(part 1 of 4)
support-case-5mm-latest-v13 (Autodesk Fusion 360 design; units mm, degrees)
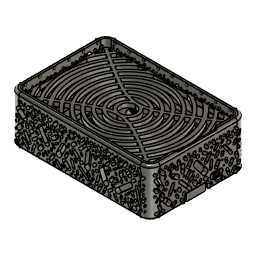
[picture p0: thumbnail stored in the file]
parameter "thick" = 1.5
sketch "Sketch1" plane through (0, 0, 0) normal (0, 0, 1) x axis (1, 0, 0)
  line L1 (86.9, 56.002) -> (1.9, 56.002)
  line L2 (86.9, -0.0138) -> (86.9, 56.002)
  line L3 (1.9, -0.0138) -> (86.9, -0.0138)
  line L4 (1.9, 56.002) -> (1.9, -0.0138)
  line L5 (0.9, 57.002) -> (0.9, -1.0138)
  line L6 (87.9, 57.002) -> (0.9, 57.002)
  line L7 (87.9, -1.0138) -> (87.9, 57.002)
  line L8 (0.9, -1.0138) -> (87.9, -1.0138)
  line L9 (-1.9, 59.802) -> (-1.9, -3.8138)
  line L10 (90.7, 59.802) -> (-1.9, 59.802)
  line L11 (90.7, -3.8138) -> (90.7, 59.802)
  line L12 (-1.9, -3.8138) -> (90.7, -3.8138)
  line L13 (-0.1, -2.0138) -> (88.9, -2.0138)
  line L14 (-0.1, 58.002) -> (-0.1, -2.0138)
  line L15 (88.9, 58.002) -> (-0.1, 58.002)
  line L16 (88.9, -2.0138) -> (88.9, 58.002)
  horizontal L1
  vertical L2
  horizontal L3
  vertical L4
  dimension "d2" = -1
  dimension "d3" = -3.8 (= "-1 mm - 2.8 mm")
  dimension "d4" = -2
extrude "Extrude1" new body sketch "Sketch1" profile of L8 L5 L6 L7 L12 L9 L10 L11 L14 L13 L15 L16 along normal blind 20
sketch "Sketch2" plane through (0, 0, 0) normal (1, 0, 0) x axis (0, 1, 0)
  line L1 (40.9881, 18.9973) -> (54.0881, 18.9973)
  line L2 (40.9881, 2.9973) -> (40.9881, 18.9973)
  line L3 (54.0881, 2.9973) -> (40.9881, 2.9973)
  line L4 (54.0881, 18.9973) -> (54.0881, 2.9973)
  line L5 (22.95, 19) -> (36.05, 19)
  line L6 (22.95, 3) -> (22.95, 19)
  line L7 (36.05, 3) -> (22.95, 3)
  line L8 (36.05, 19) -> (36.05, 3)
  line L9 (2.05, 3) -> (17.95, 3)
  line L10 (2.05, 16.5) -> (2.05, 3)
  line L11 (17.95, 16.5) -> (2.05, 16.5)
  line L12 (17.95, 3) -> (17.95, 16.5)
  point P2 (54.0881, 18.9973)
  point P3 (40.9881, 18.9973)
  point P5 (54.0881, 2.9973)
  point P6 (36.05, 19)
  point P7 (22.95, 19)
  point P9 (36.05, 3)
  point P10 (17.95, 3)
  point P11 (2.05, 3)
  point P13 (17.95, 16.5)
  horizontal L1
  vertical L2
  horizontal L3
  vertical L4
  horizontal L5
  vertical L6
  horizontal L7
  vertical L8
  horizontal L9
  vertical L10
  horizontal L11
  vertical L12
  dimension "d7" distance P2 P3 = 13.1
  dimension "d8" distance P2 P5 = 16
  dimension "d9" distance P6 P7 = 13.1
  dimension "d10" distance P6 P9 = 16
  dimension "d11" distance P10 P11 = 15.9
  dimension "d12" distance P10 P13 = 13.5
work_plane "WorkPlane1" AlongDistance 57
sketch "Sketch3" plane through (0, 57, 0) normal (0, 1, 0) x axis (1, 0, 0)
  line L1 (43.9, -6) -> (51, -6)
  line L2 (43.9, -3) -> (43.9, -6)
  line L3 (51, -3) -> (43.9, -3)
  line L4 (51, -6) -> (51, -3)
  line L5 (57.25, -6) -> (64.35, -6)
  line L6 (57.25, -3) -> (57.25, -6)
  line L7 (64.35, -3) -> (57.25, -3)
  line L8 (64.35, -6) -> (64.35, -3)
  line L9 (71.05, -6.3) -> (80.05, -6.3)
  line L10 (71.05, -3) -> (71.05, -6.3)
  line L11 (80.05, -3) -> (71.05, -3)
  line L12 (80.05, -6.3) -> (80.05, -3)
  circle C1 centre (33.2511, -6.0518) radius 3
  point P3 (51, -6)
  point P4 (43.9, -6)
  point P6 (51, -3)
  point P7 (64.35, -6)
  point P8 (57.25, -6)
  point P11 (80.05, -6.3)
  point P12 (71.05, -6.3)
  point P14 (80.05, -3)
  horizontal L1
  vertical L2
  horizontal L3
  vertical L4
  horizontal L5
  vertical L6
  horizontal L7
  vertical L8
  horizontal L9
  vertical L10
  horizontal L11
  vertical L12
  dimension "d14" diameter C1 = 6
  dimension "d15" distance P3 P4 = 7.1
  dimension "d16" distance P3 P6 = 3
  dimension "d17" distance P7 P8 = 7.1
  dimension "d18" distance P11 P12 = 9
  dimension "d19" distance P11 P14 = 3.3
work_plane "WorkPlane2" AlongDistance 87
sketch "Sketch4" plane through (87, 0, 0) normal (1, 0, 0) x axis (0, 1, 0)
  line L1 (34.6, 1.4) -> (19.9875, 1.4)
  line L2 (34.6, 0) -> (34.6, 1.4)
  line L3 (19.9875, 0) -> (34.6, 0)
  line L4 (19.9875, 1.4) -> (19.9875, 0)
  horizontal L1
  vertical L2
  horizontal L3
  vertical L4
fillet "Fillet1" radius 3.5 6.5
extrude "Extrude2" cut sketch "Sketch3" along normal blind 18
extrude "Extrude3" add sketch "Sketch1" profile of L1 L2 L3 L4 L8 L5 L6 L7 blind -2.8
sketch "Sketch5" plane through (0, 0, 0) normal (0, 0, 1) x axis (1, 0, 0)
  circle C1 centre (83.4, 52.5) radius 3
  circle C2 centre (25.4038, 52.5109) radius 3
  circle C3 centre (25.4086, 3.5211) radius 3
  circle C4 centre (83.4, 3.5) radius 3
  dimension "d27" diameter C1 = 6
  dimension "d28" diameter C2 = 6
  dimension "d29" diameter C3 = 6
  dimension "d30" diameter C4 = 6
extrude "Extrude4" add sketch "Sketch5" along normal blind 1.4
sketch "Sketch6" plane through (0, 0, 1.4) normal (0, 0, 1) x axis (-1, 0, 0)
  circle C1 centre (-83.4, -52.5) radius 3
  circle C2 centre (-25.4086, -3.5211) radius 1.375
  circle C3 centre (-25.4086, -3.5211) radius 3
  circle C4 centre (-83.4, -3.5) radius 1.375
  circle C5 centre (-83.4, -3.5) radius 3
  circle C6 centre (-83.4, -52.5) radius 1.375
  circle C7 centre (-25.4038, -52.5109) radius 1.375
  circle C8 centre (-25.4038, -52.5109) radius 3
  concentric C2 C3
  concentric C4 C5
  concentric C1 C6
  concentric C7 C8
  dimension "d33" diameter C2 = 2.75
  dimension "d34" diameter C4 = 2.75
  dimension "d35" diameter C6 = 2.75
  dimension "d36" diameter C7 = 2.75
sketch "Sketch7" plane through (0, 59.802, 0) normal (0, 1, 0) x axis (-1, 0, 0)
  line L1 (-64.35, 6) -> (-64.35, 3)
  line L2 (-57.25, 6) -> (-64.35, 6)
  line L3 (-57.25, 3) -> (-57.25, 6)
  line L4 (-64.35, 3) -> (-57.25, 3)
  line L5 (-51, 6) -> (-51, 3)
  line L6 (-43.9, 6) -> (-51, 6)
  line L7 (-43.9, 3) -> (-43.9, 6)
  line L8 (-51, 3) -> (-43.9, 3)
  line L9 (-80.05, 6.3) -> (-80.05, 3)
  line L10 (-71.05, 6.3) -> (-80.05, 6.3)
  line L11 (-71.05, 3) -> (-71.05, 6.3)
  line L12 (-80.05, 3) -> (-71.05, 3)
  line L13 (-4.6, -2.8) -> (-84.2, -2.8)
  line L14 (-84.2, 20) -> (-4.6, 20)
  line L15 (-83.55, 3) -> (-80.05, 3)
  line L16 (-83.55, -0.5) -> (-83.55, 3)
  line L17 (-80.05, -0.5) -> (-83.55, -0.5)
  line L18 (-80.05, 3) -> (-80.05, -0.5)
  line L19 (-31.1297, 8.1731) -> (-33.2511, 6.0518)
  line L20 (-30.2511, 6.0518) -> (-33.2511, 6.0518)
  line L21 (-26.7507, 8.1731) -> (-31.1297, 8.1731)
  line L22 (-26.7507, 12.5521) -> (-26.7507, 8.1731)
  line L23 (-31.1297, 12.5521) -> (-26.7507, 12.5521)
  line L24 (-31.1297, 8.1731) -> (-31.1297, 12.5521)
  line L25 (-26.7507, -0.5) -> (-83.55, -0.5)
  line L26 (-26.7507, 12.5521) -> (-26.7507, -0.5)
  line L27 (-83.55, 12.5521) -> (-26.7507, 12.5521)
  line L28 (-83.55, -0.5) -> (-83.55, 12.5521)
  line L29 (-4.6, 20) -> (-4.6, -2.8)
  line L30 (-84.2, -2.8) -> (-84.2, 20)
  circle C1 centre (-33.2511, 6.0518) radius 3
  point P10 (-80.05, 3)
  point P19 (-80.05, 3)
  point P14 (-33.2511, 6.0518)
  point P23 (-33.2511, 6.0518)
  point P24 (-31.1297, 8.1731)
  point P20 (-83.55, 3)
  point P22 (-80.05, -0.5)
  point P26 (-26.7507, 8.1731)
  point P28 (-31.1297, 12.5521)
  horizontal L15
  vertical L16
  horizontal L17
  vertical L18
  coincident P10 P19
  horizontal L20
  coincident P14 P23
  coincident C1 P24
  horizontal L21
  vertical L22
  horizontal L23
  vertical L24
  horizontal L25
  vertical L26
  horizontal L27
  vertical L28
  dimension "d37" distance P19 P20 = 3.5
  dimension "d38" distance P19 P22 = 3.5
  dimension "d39" angle L19 L20 = 45
  dimension "d40" distance P24 P26 = 4.379 (= "3.5 mm - 2.621 mm + 3.5 mm")
  dimension "d41" distance P24 P28 = 4.379 (= "4 mm + 3.5 mm - 3.121 mm")
extrude "Extrude5" cut sketch "Sketch7" profile of L1 L2 L3 L4 L5 L6 L7 L8 L9 L10 L11 L12 C1 L15 L16 L17 L18 L21 L22 L23 L24 L25 L26 L27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 against normal blind 1.8
extrude "Extrude6" cut sketch "Sketch2" against normal blind 10 and along normal blind 5
extrude "Extrude7" add of existing geometry blind 3.1
fillet "Fillet2" radius 1.5
offset_faces "OffsetFaces1" distance -0.5
offset_faces "OffsetFaces2" distance -0.5
offset_faces "OffsetFaces3" distance -0.5
sketch "Sketch8" plane through (-1.9, 0, 0) normal (-1, 0, 0) x axis (0, -1, 0)
  line L1 (-53.302, 21.6) -> (-2.6862, 21.6)
  line L2 (-2.6862, -2.8) -> (-53.302, -2.8)
  line L3 (-40.4881, 19.4973) -> (-53.302, 19.4973)
  line L4 (-40.4881, 2.4973) -> (-40.4881, 19.4973)
  line L5 (-53.302, 2.4973) -> (-40.4881, 2.4973)
  line L6 (-22.45, 19.5) -> (-36.55, 19.5)
  line L7 (-22.45, 2.5) -> (-22.45, 19.5)
  line L8 (-36.55, 2.5) -> (-22.45, 2.5)
  line L9 (-36.55, 19.5) -> (-36.55, 2.5)
  line L10 (-18.45, 2.5) -> (-2.6862, 2.5)
  line L11 (-18.45, 17) -> (-18.45, 2.5)
  line L12 (-2.6862, 17) -> (-18.45, 17)
  line L13 (-59.302, 21.6) -> (-53.302, 21.6)
  line L14 (-53.302, 21.6) -> (-53.302, 19.5)
  line L15 (-56.302, 19.4973) -> (-53.302, 19.4973)
  line L16 (-56.302, 21.4973) -> (-56.302, 19.4973)
  line L17 (-53.302, 21.4973) -> (-56.302, 21.4973)
  line L18 (-53.302, 19.4973) -> (-53.302, 21.4973)
  line L19 (0.3138, 2.5) -> (-2.6862, 2.5)
  line L20 (0.3138, 0.5) -> (0.3138, 2.5)
  line L21 (-2.6862, 0.5) -> (0.3138, 0.5)
  line L22 (-2.6862, 2.5) -> (-2.6862, 0.5)
  line L23 (-56.302, 0.5) -> (0.3138, 0.5)
  line L24 (-56.302, 21.4973) -> (-56.302, 0.5)
  line L25 (0.3138, 21.4973) -> (-56.302, 21.4973)
  line L26 (0.3138, 0.5) -> (0.3138, 21.4973)
  line L27 (-53.302, 19.4973) -> (-53.302, 21.6)
  line L28 (-53.302, -2.8) -> (-53.302, 2.4973)
  line L29 (-2.6862, 2.5) -> (-2.6862, -2.8)
  line L30 (-2.6862, 21.6) -> (-2.6862, 17)
  point P3 (-53.302, 21.6)
  point P18 (-53.302, 21.6)
  point P6 (-53.302, 19.4973)
  point P21 (-53.302, 19.4973)
  point P15 (-2.6862, 2.5)
  point P25 (-2.6862, 2.5)
  point P22 (-56.302, 19.4973)
  point P24 (-53.302, 21.4973)
  point P26 (0.3138, 2.5)
  point P28 (-2.6862, 0.5)
  horizontal L13
  vertical L14
  coincident P3 P18
  horizontal L15
  vertical L16
  horizontal L17
  vertical L18
  coincident P6 P21
  horizontal L19
  vertical L20
  horizontal L21
  vertical L22
  coincident P15 P25
  horizontal L23
  vertical L24
  horizontal L25
  vertical L26
  dimension "d59" distance P21 P22 = 3
  dimension "d60" distance P21 P24 = 2
  dimension "d61" distance P25 P26 = 3
  dimension "d62" distance P25 P28 = 2
extrude "Extrude8" cut sketch "Sketch8" profile of L3 L4 L5 L6 L7 L8 L9 L10 L11 L12 L15 L16 L17 L18 L19 L20 L21 L22 L23 L24 L25 L26 against normal blind 1.8
fillet "Fillet3" radius 3
fillet "Fillet4" radius 1.5
fillet "Fillet5" radius 0.5
fillet "Fillet6" radius 3
fillet "Fillet7" radius 1.5
fillet "Fillet8" radius 0.5
offset_faces "OffsetFaces4" distance -0.5
fillet "Fillet9" radius 0.5
offset_faces "OffsetFaces5" distance -0.5
fillet "Fillet10" radius 0.5
extrude "Extrude9" cut sketch "Sketch4" along normal blind 9.1
sketch "Sketch9" plane through (0, 0, 0) normal (0, 0, 1) x axis (-1, 0, 0)
  line L1 (-87.9, -53.502) -> (-87.9, -34.6)
  line L2 (-4.4, -57.002) -> (-84.4, -57.002)
  line L3 (-0.9, -2.4862) -> (-0.9, -53.502)
  line L4 (-84.4, 1.0138) -> (-4.4, 1.0138)
  line L5 (-87.9, -19.9875) -> (-87.9, -2.4862)
  line L6 (-90.7, -19.9875) -> (-87.9, -19.9875)
  line L7 (-90.7, -34.6) -> (-90.7, -19.9875)
  line L8 (-87.9, -34.6) -> (-90.7, -34.6)
  line L9 (-84.9, -19.9875) -> (-87.9, -19.9875)
  line L10 (-84.9, -34.6) -> (-84.9, -19.9875)
  line L11 (-87.9, -34.6) -> (-84.9, -34.6)
  line L12 (-87.9, -19.9875) -> (-87.9, -34.6)
  arc A1 centre (-84.4, -53.502) radius 3.5 clockwise from (-84.4, -57.002) to (-87.9, -53.502)
  arc A2 centre (-4.4, -53.502) radius 3.5 clockwise from (-0.9, -53.502) to (-4.4, -57.002)
  arc A3 centre (-4.4, -2.4862) radius 3.5 clockwise from (-4.4, 1.0138) to (-0.9, -2.4862)
  arc A4 centre (-84.4, -2.4862) radius 3.5 clockwise from (-87.9, -2.4862) to (-84.4, 1.0138)
  circle C1 centre (-83.4, -52.5) radius 3
  circle C2 centre (-25.4038, -52.5109) radius 3
  circle C3 centre (-83.4, -3.5) radius 3
  circle C4 centre (-25.4086, -3.5211) radius 3
  point P15 (-87.9, -19.9875)
  point P22 (-87.9, -19.9875)
  horizontal L9
  vertical L10
  horizontal L11
  vertical L12
  coincident P15 P22
  dimension "d87" distance L10 L12 = 3
extrude "Extrude10" cut sketch "Sketch9" profile of L6 L7 L8 L9 L10 L11 L12 against normal blind 6
sketch "Sketch10" plane through (0, 0, 0) normal (0, 0, 1) x axis (-1, 0, 0)
  line L1 (-84.9, -19.9875) -> (-87.9, -19.9875)
  line L2 (-84.9, -34.6) -> (-84.9, -19.9875)
  line L3 (-87.9, -34.6) -> (-84.9, -34.6)
  line L4 (-87.9, -53.502) -> (-87.9, -34.6)
  line L5 (-4.4, -57.002) -> (-84.4, -57.002)
  line L6 (-0.9, -2.4862) -> (-0.9, -53.502)
  line L7 (-84.4, 1.0138) -> (-4.4, 1.0138)
  line L8 (-87.9, -19.9875) -> (-87.9, -2.4862)
  line L9 (-69.4, -19.9875) -> (-87.9, -19.9875)
  line L10 (-69.4, -34.6) -> (-69.4, -19.9875)
  line L11 (-87.9, -34.6) -> (-69.4, -34.6)
  line L12 (-87.9, -19.9875) -> (-87.9, -34.6)
  line L13 (-87.9, -19.9875) -> (-69.4, -19.9875)
  line L14 (-87.9, -18.9875) -> (-87.9, -19.9875)
  line L15 (-69.4, -18.9875) -> (-87.9, -18.9875)
  line L16 (-69.4, -19.9875) -> (-69.4, -18.9875)
  line L17 (-87.9, -34.6) -> (-69.4, -34.6)
  line L18 (-87.9, -35.6) -> (-87.9, -34.6)
  line L19 (-69.4, -35.6) -> (-87.9, -35.6)
  line L20 (-69.4, -34.6) -> (-69.4, -35.6)
  circle C1 centre (-25.4086, -3.5211) radius 3
  circle C2 centre (-83.4, -3.5) radius 3
  circle C3 centre (-25.4038, -52.5109) radius 3
  circle C4 centre (-83.4, -52.5) radius 3
  arc A1 centre (-84.4, -53.502) radius 3.5 clockwise from (-84.4, -57.002) to (-87.9, -53.502)
  arc A2 centre (-4.4, -53.502) radius 3.5 clockwise from (-0.9, -53.502) to (-4.4, -57.002)
  arc A3 centre (-4.4, -2.4862) radius 3.5 clockwise from (-4.4, 1.0138) to (-0.9, -2.4862)
  arc A4 centre (-84.4, -2.4862) radius 3.5 clockwise from (-87.9, -2.4862) to (-84.4, 1.0138)
  point P6 (-87.9, -19.9875)
  point P22 (-87.9, -19.9875)
  point P23 (-69.4, -19.9875)
  point P26 (-87.9, -19.9875)
  point P28 (-69.4, -18.9875)
  point P24 (-69.4, -34.6)
  point P31 (-69.4, -35.6)
  horizontal L9
  vertical L10
  horizontal L11
  vertical L12
  coincident P6 P22
  horizontal L13
  vertical L14
  horizontal L15
  vertical L16
  horizontal L17
  vertical L18
  horizontal L19
  vertical L20
  dimension "d88" distance L10 L12 = 18.5
  dimension "d89" distance P23 P26 = 18.5
  dimension "d90" distance P23 P28 = 1
  dimension "d91" distance P24 P31 = 1
extrude "Extrude11" cut sketch "Sketch10" profile of L1 L2 L3 L4 L8 L9 L10 L11 L13 L14 L15 L16 L17 L18 L19 L20 against normal blind 1
fillet "Fillet11" radius 1
fillet "Fillet15" radius 1
fillet "Fillet16" radius 1
sketch "IZA" plane through (0, -3.8138, 0) normal (0, -1, 0) x axis (1, 0, 0)
  line L1 (84.2, -1.8) -> (4.6, -1.8)
  line L2 (4.6, 21.6) -> (84.2, 21.6)
  line L3 (84.2, 21.6) -> (4.6, 21.6)
  line L4 (44.4, 40) -> (44.4, 21.6)
  line L5 (41.1449, 20.8299) -> (44.8249, 16.8432)
  line L6 (43.6547, 15.763) -> (39.9747, 19.7497)
  line L7 (66.2842, 20.3207) -> (65.9781, 17.5299)
  line L8 (4.6, -1.8) -> (84.2, -1.8)
  line L9 (64.5596, 17.6854) -> (64.8657, 20.4763)
  line L10 (84.2, 21.6) -> (4.6, 21.6)
  line L11 (71.6539, 20.4351) -> (71.6228, 19.3406)
  line L12 (70.7982, 19.364) -> (70.8292, 20.4585)
  line L13 (81.018, 7.4967) -> (78.2927, 3.0866)
  line L14 (13.972, 4.6757) -> (11.5299, 7.4209)
  line L15 (72.6309, 5.8742) -> (72.5955, 5.5374)
  line L16 (12.158, 7.9796) -> (14.6001, 5.2345)
  line L17 (19.0812, -0.1017) -> (20.8011, 2.1505)
  line L18 (7.4152, 4.3046) -> (6.9567, 5.4263)
  line L19 (3.141, 9.3206) -> (3.8694, 6.9866)
  line L20 (73.0015, 9.0172) -> (75.3087, 6.9992)
  line L21 (2.3688, 6.5182) -> (1.6404, 8.8522)
  line L22 (21.9671, 1.2601) -> (20.2472, -0.9921)
  line L23 (83.553, 11.3545) -> (85.4309, 9.0757)
  line L24 (83.7361, 13.1487) -> (82.8858, 13.922)
  line L25 (61.845, -0.1192) -> (61.2785, -1.2415)
  line L26 (10.1269, -0.5839) -> (11.6138, 2.3233)
  line L27 (28.3157, -1.213) -> (26.695, 2.4711)
  line L28 (79.3759, 17.2446) -> (83.0491, 20.2716)
  line L29 (23.7268, 4.2977) -> (25.7268, 2.2977)
  line L30 (2.0341, 16.1849) -> (2.4342, 16.8326)
  line L31 (3.2544, 14.2814) -> (4.1316, 12.8648)
  line L32 (9.2223, 3.1069) -> (9.5889, 4.6763)
  line L33 (9.2346, 14.6077) -> (7.6497, 15.8079)
  line L34 (3.2227, 12.3021) -> (2.3456, 13.7186)
  line L35 (24.7268, 1.2977) -> (22.7268, 3.2977)
  line L36 (3.1364, 18.7692) -> (2.0102, 20.036)
  line L37 (85.3174, 17.5191) -> (81.6442, 14.492)
  line L38 (82.1114, 2.9002) -> (78.9433, -0.5829)
  line L39 (8.5696, 7.6651) -> (9.4427, 9.3274)
  line L40 (5.8284, 16.871) -> (5.4007, 15.04)
  line L41 (4.5263, 2.1734) -> (6.0799, -0.331)
  line L42 (76.3332, 4.2976) -> (79.0585, 8.7076)
  line L43 (5.0423, -0.9746) -> (3.4887, 1.5298)
  line L44 (3.1341, 16.4003) -> (2.7341, 15.7526)
  line L45 (10.9333, 8.5445) -> (10.0601, 6.8822)
  line L46 (10.8556, 4.3804) -> (10.489, 2.811)
  line L47 (4.096, 15.3449) -> (4.5238, 17.1758)
  line L48 (75.8256, 9.1619) -> (74.623, 10.2557)
  line L49 (74.2041, 5.7363) -> (71.8969, 7.7542)
  line L50 (8.2741, 5.9648) -> (8.7327, 4.8431)
  line L51 (77.5028, 0.7274) -> (80.6708, 4.2104)
  line L52 (83.4401, 14.5315) -> (84.2904, 13.7582)
  line L53 (1.8665, 0.8131) -> (1.5468, 1.8376)
  line L54 (2.1882, 2.0377) -> (2.5079, 1.0133)
  line L55 (47.4316, -0.4539) -> (46.9137, -1.2135)
  line L56 (25.9694, 15.576) -> (24.847, 17.3307)
  line L57 (37.3701, 4.6155) -> (38.4635, 5.7966)
  line L58 (37.4886, 8.0899) -> (36.5702, 16.4568)
  line L59 (61.268, 12.4847) -> (58.7171, 14.6614)
  line L60 (7.7819, 13.4084) -> (5.5432, 3.8264)
  line L61 (63.2863, 7.4674) -> (63.2863, 6)
  line L62 (13.0569, 14.2814) -> (13.7792, 15.5697)
  line L63 (58.7321, 12.7384) -> (60.2408, 11.9079)
  line L64 (28.9566, 14.9931) -> (28.0579, 14.4182)
  line L65 (27.6151, 15.1105) -> (28.5138, 15.6853)
  line L66 (60.1963, 16.3949) -> (62.7472, 14.2182)
  line L67 (4.6, 21.6) -> (4.6, -1.8)
  line L68 (39.49, 4.8465) -> (38.3966, 3.6653)
  line L69 (14.8629, 14.9621) -> (14.1406, 13.6739)
  line L70 (35.0363, 6) -> (35.0363, 8.185)
  line L71 (62.5376, 10.1007) -> (61.5172, 8.247)
  line L72 (16.1273, 11.2122) -> (16.1273, 12.4085)
  line L73 (36.1927, 8.185) -> (36.1927, 6)
  line L74 (30.6878, 3.2579) -> (32.4973, -0.1273)
  line L75 (31.1027, -0.8727) -> (29.2933, 2.5125)
  line L76 (17.4293, 12.4085) -> (17.4293, 11.2122)
  line L77 (60.4573, 8.8305) -> (61.4777, 10.6841)
  line L78 (82.7717, 0.2) -> (81.4822, 0.2)
  line L79 (12.8782, 1.6767) -> (11.3914, -1.2306)
  line L80 (4.6, 21.6) -> (84.2, 21.6)
  line L81 (86.8678, 11.0442) -> (86.3856, 10.6468)
  line L82 (82.3348, 0.9607) -> (82.7717, 0.2)
  line L83 (84.6981, -0.7837) -> (85.0487, 0.1922)
  line L84 (83.4233, 7.4213) -> (81.5454, 9.7001)
  line L85 (85.7782, 11.3839) -> (86.2604, 11.7813)
  line L86 (16.646, 1.5239) -> (16.2289, 3.2118)
  line L87 (70.9499, 1.055) -> (72.2492, -0.6596)
  line L88 (2.2146, 5.4077) -> (2.5694, 4.2706)
  line L89 (1.805, 4.0321) -> (1.4502, 5.1691)
  line L90 (85.0487, 0.1922) -> (86.4094, 0.1962)
  line L91 (82.3321, -1.2797) -> (81.4927, 0.1817)
  line L92 (71.3508, -1.3404) -> (70.0515, 0.3742)
  line L93 (85.3325, 13.697) -> (85.3325, 15.2435)
  line L94 (15.1271, 3) -> (15.1271, 1)
  line L95 (86.4094, 0.1962) -> (85.9019, -1.2163)
  line L96 (13.9875, 1) -> (13.9875, 3)
  line L97 (81.4822, 0.2) -> (81.3652, 0.4038)
  line L98 (85.6278, 2.3323) -> (83.7619, 4.0295)
  line L99 (82.7801, 0.1855) -> (83.3017, -0.7227)
  line L100 (17.3811, 3.4966) -> (17.7982, 1.8087)
  line L101 (74.4989, 3.8647) -> (75.9777, -0.3704)
  line L102 (69.5322, 2.5703) -> (68.0697, 4.645)
  line L103 (86.5634, 0.6249) -> (86.4108, 0.2)
  line L104 (81.4927, 0.1817) -> (82.7801, 0.1855)
  line L105 (86.3892, 15.2435) -> (86.3892, 13.697)
  line L106 (86.4108, 0.2) -> (85.0515, 0.2)
  line L107 (84.9422, 5.3272) -> (86.8082, 3.63)
  line L108 (85.0515, 0.2) -> (85.3595, 1.0574)
  line L109 (74.5993, -0.8517) -> (73.1205, 3.3834)
  line L110 (68.711, 1.7551) -> (68.714, 0.7244)
  line L111 (49.938, -1.4028) -> (48.9639, -0.3475)
  line L112 (33.339, 16.367) -> (34.609, 18.0036)
  line L113 (71.3449, 11.5288) -> (72.4314, 12.363)
  line L114 (49.5212, 0.167) -> (50.4953, -0.8883)
  line L115 (31.5771, 18.3818) -> (30.6393, 17.2029)
  line L116 (26.8825, 12.574) -> (25.9982, 11.1455)
  line L117 (26.1612, 18.1713) -> (27.2836, 16.4166)
  line L118 (28.7687, 19.65) -> (27.6761, 18.9511)
  line L119 (61.1429, 19.6723) -> (61.381, 17.6387)
  line L120 (73.2637, 11.2788) -> (72.1773, 10.4446)
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  point P5 (4.6, 21.6)
  point P6 (4.6, 21.6)
  point P4 (84.2, 21.6)
  point P7 (84.2, 21.6)
  point P8 (44.4, 21.6)
  point P1 (0, 0)
  point P275 (88.8, 0)
  point P2 (4.6, -1.8)
  point P241 (84.2, -1.8)
  point P3 (84.2, -1.8)
  point P133 (4.6, -1.8)
  point P629 (4.6, 21.6)
  point P128 (84.2, 21.6)
  point P29 (84.2, 21.6)
  point P23 (4.6, 21.6)
  point P30 (44.4, 21.6)
  coincident P5 P6
  coincident P4 P7
  midpoint L3 P8
  perpendicular L3 L4
  symmetric P1 L4 P275
  symmetric P2 L4 P241
  symmetric P3 L4 P133
  symmetric P4 L4 P629
  symmetric P5 L4 P128
  symmetric P6 L4 P29
  symmetric P7 L4 P23
  symmetric P8 L4 P30
sketch "Sketch13" plane through (0, -3.8138, 0) normal (0, -1, 0) x axis (1, 0, 0)
  line L1 (1.1, 0.2) -> (15.4333, 0.2)
  line L2 (1.1, 21.41) -> (1.1, 0.2)
  line L3 (15.4333, 21.41) -> (1.1, 21.41)
  line L4 (15.4333, 0.2) -> (15.4333, 21.41)
  line L5 (87.7164, 21.41) -> (1.1, 21.41)
  line L6 (87.6811, -0.0555) -> (1.1, 0.2)
  line L7 (7.1558, 14.492) -> (3.4826, 17.5191)
  line L8 (5.7509, 20.2716) -> (9.4241, 17.2446)
  line L9 (8.29, 15.8683) -> (4.6167, 18.8953)
  line L10 (3.3691, 9.0757) -> (5.247, 11.3545)
  line L11 (7.2546, 9.7001) -> (5.3767, 7.4213)
  line L12 (4.3729, 8.2485) -> (6.2508, 10.5273)
  line L13 (35.3987, 11.8256) -> (32.1336, 5.3974)
  line L14 (29.2059, 6.8845) -> (32.471, 13.3127)
  line L15 (33.9349, 12.5691) -> (30.6697, 6.1409)
  line L16 (21.6738, 7.836) -> (17.4563, 14.9568)
  line L17 (20.0749, 16.5077) -> (24.2924, 9.387)
  line L18 (22.9831, 8.6115) -> (18.7656, 15.7322)
  line L19 (47.7811, 8.4774) -> (48.6994, 16.8443)
  line L20 (52.2298, 16.4568) -> (51.3114, 8.0899)
  line L21 (49.5463, 8.2837) -> (50.4646, 16.6506)
  line L22 (78.7007, 11.1498) -> (70.1868, 3.6277)
  line L23 (68.2015, 5.8748) -> (76.7153, 13.3969)
  line L24 (77.708, 12.2734) -> (69.1941, 4.7512)
  line L25 (10.5073, 3.0866) -> (7.782, 7.4967)
  line L26 (9.7415, 8.7076) -> (12.4668, 4.2976)
  line L27 (11.4871, 3.6921) -> (8.7618, 8.1021)
  line L28 (26.0528, 14.2182) -> (28.6037, 16.3949)
  line L29 (30.0829, 14.6614) -> (27.532, 12.4847)
  line L30 (26.7924, 13.3514) -> (29.3433, 15.5282)
  line L31 (20.7303, 4.645) -> (19.2678, 2.5703)
  line L32 (17.243, 3.9976) -> (18.7055, 6.0723)
  line L33 (19.7179, 5.3587) -> (18.2554, 3.2839)
  line L34 (39.9502, 7.8503) -> (41.4467, 3.8885)
  line L35 (39.9597, 3.3268) -> (38.4632, 7.2886)
  line L36 (39.2067, 7.5694) -> (40.7032, 3.6076)
  line L37 (39.0464, 16.8356) -> (40.9491, 18.705)
  line L38 (42.3165, 17.3132) -> (40.4137, 15.4438)
  line L39 (39.73, 16.1397) -> (41.6328, 18.0091)
  line L40 (31.2069, 16.641) -> (29.6142, 18.4111)
  line L41 (31.601, 20.1987) -> (33.1937, 18.4287)
  line L42 (32.2003, 17.5349) -> (30.6076, 19.3049)
  line L43 (22.8219, 17.5299) -> (22.5158, 20.3207)
  line L44 (23.9343, 20.4763) -> (24.2404, 17.6854)
  line L45 (23.5311, 17.6076) -> (23.225, 20.3985)
  line L46 (13.2909, 13.1537) -> (11.8323, 14.3757)
  line L47 (13.2506, 16.0684) -> (14.7091, 14.8463)
  line L48 (14, 14) -> (12.5415, 15.2221)
  line L49 (14.177, 10.2557) -> (12.9744, 9.1619)
  line L50 (11.6205, 10.6504) -> (12.823, 11.7443)
  line L51 (13.5, 11) -> (12.2974, 9.9062)
  line L52 (9.8567, -0.5829) -> (6.6886, 2.9002)
  line L53 (8.1292, 4.2104) -> (11.2972, 0.7274)
  line L54 (10.577, 0.0722) -> (7.4089, 3.5553)
  line L55 (1.9918, 3.63) -> (3.8578, 5.3272)
  line L56 (5.0381, 4.0295) -> (3.1722, 2.3323)
  line L57 (2.582, 2.9812) -> (4.4479, 4.6784)
  line L58 (28.1972, 4.0188) -> (26.4966, 1.0598)
  line L59 (24.9114, 1.9708) -> (26.612, 4.9299)
  line L60 (27.4046, 4.4743) -> (25.704, 1.5153)
  line L61 (22.9063, 1.7315) -> (21.4727, 3.3705)
  line L62 (22.253, 4.053) -> (23.6865, 2.414)
  line L63 (23.2964, 2.0728) -> (21.8629, 3.7117)
  line L64 (13.4913, 6.9992) -> (15.7985, 9.0172)
  line L65 (16.9031, 7.7542) -> (14.5959, 5.7363)
  line L66 (14.0436, 6.3677) -> (16.3508, 8.3857)
  line L67 (13.0808, 20.9744) -> (14.4245, 18.7058)
  line L68 (13.2148, 17.9893) -> (11.8711, 20.2579)
  line L69 (12.476, 20.6162) -> (13.8196, 18.3476)
  line L70 (17.9708, 20.4585) -> (18.0018, 19.364)
  line L71 (17.1772, 19.3406) -> (17.1461, 20.4351)
  line L72 (17.5584, 20.4468) -> (17.5895, 19.3523)
  line L73 (27.3223, 10.6841) -> (28.3427, 8.8305)
  line L74 (27.2828, 8.247) -> (26.2624, 10.1007)
  line L75 (26.7924, 10.3924) -> (27.8127, 8.5388)
  line L76 (28.5592, 11.9079) -> (30.0679, 12.7384)
  line L77 (30.5913, 11.7877) -> (29.0825, 10.9571)
  line L78 (28.8208, 11.4325) -> (30.3296, 12.263)
  line L79 (26.4863, 7.4674) -> (26.4863, 6)
  line L80 (25.5137, 6) -> (25.5137, 7.4674)
  line L81 (26, 7.4674) -> (26, 6)
  line L82 (24.0017, 3.8795) -> (23.631, 4.8606)
  line L83 (24.369, 5.1394) -> (24.7396, 4.1582)
  line L84 (24.3706, 4.0188) -> (24, 5)
  line L85 (11.0609, 13) -> (11.0609, 11.6168)
  line L86 (9.042, 11.6168) -> (9.042, 13)
  line L87 (10.0515, 13) -> (10.0515, 11.6168)
  line L88 (2.4108, 13.697) -> (2.4108, 15.2435)
  line L89 (3.4675, 15.2435) -> (3.4675, 13.697)
  line L90 (2.9391, 13.697) -> (2.9391, 15.2435)
  line L91 (5.9142, 13.922) -> (5.0639, 13.1487)
  line L92 (4.5096, 13.7582) -> (5.3599, 14.5315)
  line L93 (5.6371, 14.2267) -> (4.7868, 13.4535)
  line L94 (2.4144, 10.6468) -> (1.9322, 11.0442)
  line L95 (2.5396, 11.7813) -> (3.0218, 11.3839)
  line L96 (2.7181, 11.0154) -> (2.2359, 11.4127)
  line L97 (59.6907, 4.9916) -> (57.2063, 11.2928)
  line L98 (60.7937, 12.7072) -> (63.2781, 6.406)
  line L99 (61.4844, 5.6988) -> (59, 12)
  line L100 (66.2568, 15.9753) -> (71.735, 20.3331)
  line L101 (72.265, 19.6669) -> (66.7868, 15.309)
  line L102 (66.5218, 15.6421) -> (72, 20)
  line L103 (82.5046, 13.7557) -> (84.7432, 4.1736)
  line L104 (83.2568, 3.8264) -> (81.0181, 13.4084)
  line L105 (81.7614, 13.582) -> (84, 4)
  line L106 (44.9386, 6.728) -> (50.6186, 2.3744)
  line L107 (49.5623, 0.9963) -> (43.8823, 5.3498)
  line L108 (44.4105, 6.0389) -> (50.0905, 1.6854)
  line L109 (57.7465, 6.7757) -> (56.2108, 1.6651)
  line L110 (54.7178, 2.1138) -> (56.2535, 7.2243)
  line L111 (57, 7) -> (55.4643, 1.8895)
  line L112 (42.8957, 9.8312) -> (39.8006, 12.6882)
  line L113 (41.4017, 14.4228) -> (44.4968, 11.5658)
  line L114 (43.6962, 10.6985) -> (40.6012, 13.5555)
  line L115 (43.9751, 16.8432) -> (47.6551, 20.8299)
  line L116 (48.8253, 19.7497) -> (45.1453, 15.763)
  line L117 (44.5602, 16.3031) -> (48.2402, 20.2898)
  line L118 (36.3197, 0.797) -> (33.6259, 3.2836)
  line L119 (35.5352, 5.3521) -> (38.2291, 2.8654)
  line L120 (37.2744, 1.8312) -> (34.5805, 4.3179)
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  point P4 (1.1, 21.41)
  point P7 (1.1, 21.41)
  point P2 (15.4333, 0.2)
  point P6 (15.4333, 0.2)
  point P8 (1.1, 21.41)
  point P670 (15.4333, 19.9748)
  point P739 (47.0856, 0.0643)
  point P762 (27.4336, 0.1223)
  point P775 (51.6891, 0.0507)
  horizontal L1
  vertical L2
  horizontal L3
  vertical L4
  coincident P4 P7
  coincident P2 P6
  coincident P7 P8
  perpendicular L2 L5
  parallel L7 L8
  parallel L10 L11
  perpendicular L8 L12
  parallel L13 L14
  parallel L16 L17
  parallel L19 L20
  parallel L22 L23
  parallel L25 L26
  parallel L28 L29
  parallel L31 L32
  parallel L34 L35
  parallel L37 L38
  parallel L40 L41
  parallel L43 L44
  parallel L46 L47
  parallel L49 L50
  parallel L52 L53
  perpendicular L49 L54
  parallel L55 L56
  perpendicular L53 L57
  parallel L58 L59
  parallel L61 L62
  parallel L64 L65
  perpendicular L62 L66
  parallel L67 L68
  parallel L18 L69
  parallel L70 L71
  parallel L73 L74
  parallel L76 L77
  perpendicular L73 L78
  parallel L79 L80
  vertical L81
  parallel L82 L83
  parallel L35 L84
  parallel L85 L86
  vertical L87
  parallel L88 L89
  vertical L90
  parallel L91 L92
  parallel L94 L95
  perpendicular L10 L96
  parallel L97 L98
  parallel L100 L101
  parallel L103 L104
  parallel L106 L107
  parallel L109 L110
  parallel L112 L113
  parallel L115 L116
  perpendicular L113 L117
  parallel L118 L119
  perpendicular L116 L120
  coincident L4 P670
  coincident L6 P739
  coincident L6 P762
  coincident L6 P775
  dimension "d138" diameter = 2
  dimension "d139" diameter = 1
  dimension "d140" diameter = 1
  dimension "d141" diameter = 1
  dimension "d142" diameter = 1
extrude "Extrude14" cut sketch "Sketch6" profile of C2 C4 C6 C7 against normal blind 3.2
extrude "Extrude15" cut of existing geometry blind -1
sketch "Sketch15" plane through (0, 59.802, 0) normal (0, 1, 0) x axis (-1, 0, 0)
  line L1 (-4.6, -1.8) -> (-84.2, -1.8)
  line L2 (-84.2, 21.6) -> (-4.6, 21.6)
  line L3 (-76.4559, 14.1193) -> (-77.6342, 15.4297)
  line L4 (-76.3658, 16.5703) -> (-75.1875, 15.2599)
  line L5 (-75.8217, 14.6896) -> (-77, 16)
  line L6 (-71.1136, 14.4052) -> (-70.2196, 17.2279)
  line L7 (-68.7804, 16.7721) -> (-69.6744, 13.9494)
  line L8 (-70.394, 14.1773) -> (-69.5, 17)
  line L9 (-59.1104, 15.8976) -> (-60.0489, 13.6858)
  line L10 (-61.2737, 14.2055) -> (-60.3352, 16.4173)
  line L11 (-59.7228, 16.1575) -> (-60.6613, 13.9457)
  line L12 (-37.2959, 15.5165) -> (-38.4848, 14.1425)
  line L13 (-40.7451, 16.0982) -> (-39.5562, 17.4722)
  line L14 (-38.4261, 16.4944) -> (-39.615, 15.1203)
  line L15 (-86.4431, 6.8926) -> (-87.4228, 9.4092)
  line L16 (-85.981, 9.9705) -> (-85.0013, 7.4539)
  line L17 (-85.4415, 6.4523) -> (-86.9826, 10.4107)
  line L18 (-84.9447, 3.133) -> (-85.2346, 2.4361)
  line L19 (-87.1061, 3.2146) -> (-86.8162, 3.9115)
  line L20 (-85.4912, 4.458) -> (-86.5596, 1.8896)
  line L21 (-85.38, -1.1165) -> (-86.1587, -0.6152)
  line L22 (-85.2629, 0.7763) -> (-84.4842, 0.275)
  line L23 (-84.2364, -0.8687) -> (-86.4066, 0.5285)
  line L24 (-4.6, 21.6) -> (-4.6, -1.8)
  line L25 (-84.2, -1.8) -> (-84.2, 21.6)
  curve K1 (-29.7507, 13.0421) -> (-26.2608, 9.5521)
  line L26 (-26.2608, 2.5) -> (-26.2608, 9.5521)
  curve K2 (-26.2608, 2.5) -> (-29.7507, -0.99)
  line L27 (-80.55, -0.99) -> (-29.7507, -0.99)
  curve K3 (-80.55, -0.99) -> (-84.04, 2.5)
  line L28 (-84.04, 9.5521) -> (-84.04, 2.5)
  curve K4 (-84.04, 9.5521) -> (-80.55, 13.0421)
  line L29 (-29.7507, 13.0421) -> (-80.55, 13.0421)
  arc A1 centre (-75.8217, 14.6896) radius 0.8529 clockwise from (-75.1875, 15.2599) to (-76.4559, 14.1193)
  arc A2 centre (-77, 16) radius 0.8529 clockwise from (-77.6342, 15.4297) to (-76.3658, 16.5703)
  arc A3 centre (-70.394, 14.1773) radius 0.7548 clockwise from (-69.6744, 13.9494) to (-71.1136, 14.4052)
  arc A4 centre (-69.5, 17) radius 0.7548 clockwise from (-70.2196, 17.2279) to (-68.7804, 16.7721)
  arc A5 centre (-59.7228, 16.1575) radius 0.6653 clockwise from (-60.3352, 16.4173) to (-59.1104, 15.8976)
  arc A6 centre (-60.6613, 13.9457) radius 0.6653 clockwise from (-60.0489, 13.6858) to (-61.2737, 14.2055)
  circle C1 centre (-51.7576, 14.1842) radius 0.8956
  arc A7 centre (-38.4261, 16.4944) radius 1.4945 clockwise from (-39.5562, 17.4722) to (-37.2959, 15.5165)
  arc A8 centre (-39.615, 15.1203) radius 1.4945 clockwise from (-38.4848, 14.1425) to (-40.7451, 16.0982)
  circle C2 centre (-46.1506, 14.6896) radius 0.6135
  circle C3 centre (-42.5, 14) radius 0.7071
  circle C4 centre (-35.8031, 14.8295) radius 0.8831
  circle C5 centre (-35.8031, 19.8874) radius 0.4919
  circle C6 centre (-24.9422, 5.7931) radius 0.908
  arc A9 centre (-85.7222, 7.1732) radius 0.7736 clockwise from (-85.0013, 7.4539) to (-86.4431, 6.8926)
  arc A10 centre (-86.7019, 9.6898) radius 0.7736 clockwise from (-87.4228, 9.4092) to (-85.981, 9.9705)
  arc A11 centre (-85.8804, 3.5223) radius 1.0135 clockwise from (-86.8162, 3.9115) to (-84.9447, 3.133)
  arc A12 centre (-86.1703, 2.8254) radius 1.0135 clockwise from (-85.2346, 2.4361) to (-87.1061, 3.2146)
  arc A13 centre (-84.9321, -0.4207) radius 0.8275 clockwise from (-84.4842, 0.275) to (-85.38, -1.1165)
  arc A14 centre (-85.7108, 0.0806) radius 0.8275 clockwise from (-86.1587, -0.6152) to (-85.2629, 0.7763)
  circle C7 centre (-87, 5.5) radius 0.4708
  circle C8 centre (-85, 11.5) radius 0.8378
  point P43 (-86.9826, 10.4107)
  point P44 (-85.4415, 6.4523)
  point P51 (-86.5596, 1.8896)
  point P52 (-85.4912, 4.458)
  point P59 (-86.4066, 0.5285)
  point P60 (-84.2364, -0.8687)
  tangent L3 A1
  tangent A1 L4
  parallel L3 L4
  tangent L4 A2
  tangent L3 A2
  tangent L6 A3
  tangent A3 L7
  parallel L6 L7
  tangent L7 A4
  tangent L6 A4
  tangent L9 A5
  tangent A5 L10
  parallel L9 L10
  tangent L10 A6
  tangent L9 A6
  tangent L12 A7
  tangent A7 L13
  parallel L12 L13
  tangent L13 A8
  tangent L12 A8
  tangent L15 A9
  tangent A9 L16
  parallel L15 L16
  tangent L16 A10
  tangent L15 A10
  midpoint A10 P43
  midpoint A9 P44
  tangent L18 A11
  tangent A11 L19
  parallel L18 L19
  tangent L19 A12
  tangent L18 A12
  midpoint A12 P51
  midpoint A11 P52
  tangent L21 A13
  tangent A13 L22
  parallel L21 L22
  tangent L22 A14
  tangent L21 A14
  midpoint A14 P59
  midpoint A13 P60
sketch "LIJEVO" plane through (90.7, 0, 0) normal (1, 0, 0) x axis (0, 1, 0)
  line L1 (19.9875, -1.8) -> (2.6862, -1.8)
  line L2 (19.9875, 0.4) -> (19.9875, -1.8)
  line L3 (33.6, 1.4) -> (20.9875, 1.4)
  line L4 (34.6, -1.8) -> (34.6, 0.4)
  line L5 (2.6862, 21.6) -> (53.302, 21.6)
  line L6 (15.0195, 14.041) -> (9.6198, 2.6702)
  line L7 (5.5809, 4.5881) -> (10.9805, 15.959)
  line L8 (13, 15) -> (7.6003, 3.6292)
  line L9 (30.7995, 7.1973) -> (25.0468, 14.723)
  line L10 (27.9687, 16.9565) -> (33.7214, 9.4309)
  line L11 (32.2604, 8.3141) -> (26.5077, 15.8398)
  line L12 (48.7945, 10.1848) -> (44.3692, 16.2124)
  line L13 (45.7595, 17.2331) -> (50.1848, 11.2055)
  line L14 (50, 10) -> (44.554, 17.4178)
  line L15 (42.1292, 10.5863) -> (43.9063, 1.5867)
  line L16 (40.9591, 1.0047) -> (39.182, 10.0043)
  line L17 (40.6556, 10.2953) -> (42.4327, 1.2957)
  line L18 (21.857, 2.9774) -> (15.2565, 10.3328)
  line L19 (16.7435, 11.6672) -> (23.3441, 4.3119)
  line L20 (22.6005, 3.6446) -> (16, 11)
  line L21 (2.8, 12.4) -> (-0.2, 18.4)
  line L22 (2.2, 19.6) -> (5.2, 13.6)
  line L23 (4, 13) -> (1, 19)
  line L24 (5.4262, 17.2734) -> (6.2526, 19.0136)
  line L25 (6.8267, 18.741) -> (6.0003, 17.0007)
  line L26 (5.7133, 17.137) -> (6.5397, 18.8773)
  line L27 (2.1349, 8.6128) -> (1.0752, 6.3813)
  line L28 (0.3368, 6.7319) -> (1.3965, 8.9634)
  line L29 (1.7657, 8.7881) -> (0.706, 6.5566)
  line L30 (2.2282, 1.6208) -> (1.2876, 3.5351)
  line L31 (2.8313, 4.2936) -> (3.7718, 2.3792)
  line L32 (3, 2) -> (2.0594, 3.9144)
  line L33 (4.1365, 7.811) -> (3.2436, 9.6284)
  line L34 (4.7564, 10.3716) -> (5.6493, 8.5543)
  line L35 (4.8929, 8.1827) -> (4, 10)
  line L36 (0.2057, 11.957) -> (-0.564, 13.5235)
  line L37 (1.0192, 14.3013) -> (1.7888, 12.7348)
  line L38 (0.9973, 12.3459) -> (0.2276, 13.9124)
  line L39 (16.4352, 16) -> (16.4352, 19.205)
  line L40 (19, 19.205) -> (19, 16)
  line L41 (17.7176, 16) -> (17.7176, 19.205)
  line L42 (21.6602, 8.983) -> (23.5887, 10.6222)
  line L43 (24.8948, 9.0855) -> (22.9663, 7.4464)
  line L44 (22.3133, 8.2147) -> (24.2417, 9.8539)
  line L45 (29.9227, 5.4667) -> (29.4636, 3.8299)
  line L46 (28.2184, 4.1791) -> (28.6775, 5.816)
  line L47 (29.3001, 5.6414) -> (28.841, 4.0045)
  line L48 (15.1274, 5.4522) -> (14.1792, 6.7632)
  line L49 (15.7324, 7.8866) -> (16.6807, 6.5756)
  line L50 (15.904, 6.0139) -> (14.9558, 7.3249)
  line L51 (8.575, 18.2125) -> (9.575, 20.2125)
  line L52 (10.425, 19.7875) -> (9.425, 17.7875)
  line L53 (9, 18) -> (10, 20)
  line L54 (6.6517, 13.5222) -> (6.2159, 14.7131)
  line L55 (7.7841, 15.2869) -> (8.2198, 14.0959)
  line L56 (7.4357, 13.809) -> (7, 15)
  line L57 (13.3209, 0.1362) -> (11.7876, -1.1001)
  line L58 (10.5526, 0.4315) -> (12.0859, 1.6678)
  line L59 (12.7034, 0.902) -> (11.1701, -0.3343)
  line L60 (4.31, -1.0078) -> (3.9008, -0.5003)
  line L61 (5.2583, 0.5943) -> (5.6676, 0.0868)
  line L62 (4.9888, -0.4605) -> (4.5796, 0.047)
  line L63 (52.5522, 0.8244) -> (51.5255, -0.7512)
  line L64 (49.759, 0.3999) -> (50.7857, 1.9756)
  line L65 (51.669, 1.4) -> (50.6422, -0.1756)
  line L66 (45.742, 6.8809) -> (45.2533, 8.8109)
  line L67 (46.7467, 9.1891) -> (47.2354, 7.259)
  line L68 (46.4887, 7.07) -> (46, 9)
  line L69 (36.1345, 0.1699) -> (36.7263, 3.4044)
  line L70 (39.4776, 2.901) -> (38.8857, -0.3335)
  line L71 (37.5101, -0.0818) -> (38.1019, 3.1527)
  line L72 (19.653, 11.6554) -> (21.3757, 14.3394)
  line L73 (22.9212, 13.3475) -> (21.1985, 10.6634)
  line L74 (20.4258, 11.1594) -> (22.1485, 13.8434)
  line L75 (20.3462, 17.6439) -> (21.7671, 19.7299)
  line L76 (23.8563, 18.3067) -> (22.4353, 16.2207)
  line L77 (21.3907, 16.9323) -> (22.8117, 19.0183)
  line L78 (13.3404, 18.7178) -> (12.8338, 19.9018)
  line L79 (14.1531, 20.4663) -> (14.6596, 19.2822)
  line L80 (14, 19) -> (13.4934, 20.1841)
  line L81 (49.5, 19) -> (48.5, 20)
  line L82 (49.5, 21) -> (50.5, 20)
  line L83 (50, 19.5) -> (49, 20.5)
  line L84 (42.7252, 20.2252) -> (43.5, 21)
  line L85 (44.5, 20) -> (43.7252, 19.2252)
  line L86 (43.2252, 19.7252) -> (44, 20.5)
  line L87 (53.3077, 15.9615) -> (52.3077, 14.4615)
  line L88 (50.6923, 15.5385) -> (51.6923, 17.0385)
  line L89 (52.5, 16.5) -> (51.5, 15)
  line L90 (47.4429, 16.5571) -> (46.75, 17.25)
  line L91 (48.25, 18.75) -> (48.9429, 18.0571)
  line L92 (48.1929, 17.3071) -> (47.5, 18)
  line L93 (42.5959, 12.7476) -> (42.9646, 14.0937)
  line L94 (44.7728, 13.5984) -> (44.4041, 12.2524)
  line L95 (43.5, 12.5) -> (43.8687, 13.8461)
  line L96 (32.0014, 14.5087) -> (34.6307, 17.7132)
  line L97 (36.3693, 16.2868) -> (33.74, 13.0822)
  line L98 (32.8707, 13.7955) -> (35.5, 17)
  line L99 (35.1719, 8.3587) -> (35.6831, 12.906)
  line L100 (37.3222, 12.7217) -> (36.811, 8.1744)
  line L101 (35.9915, 8.2665) -> (36.5027, 12.8139)
  line L102 (37.0914, 6.1817) -> (37.9207, 8.0464)
  line L103 (38.7379, 7.683) -> (37.9086, 5.8183)
  line L104 (37.5, 6) -> (38.3293, 7.8647)
  line L105 (52.5517, 6.1207) -> (51.5517, 8.6207)
  line L106 (53.4483, 9.3793) -> (54.4483, 6.8793)
  line L107 (53.5, 6.5) -> (52.5, 9)
  line L108 (48, 5) -> (49, 7)
  line L109 (51, 6) -> (50, 4)
  line L110 (49, 4.5) -> (50, 6.5)
  line L111 (46.1305, 3.9098) -> (47.6668, 1.4098)
  line L112 (46.3332, 0.5902) -> (44.7969, 3.0902)
  line L113 (45.4637, 3.5) -> (47, 1)
  line L114 (54.4917, 10.5547) -> (53.0987, 12.4521)
  line L115 (54.1184, 13.2008) -> (55.5115, 11.3033)
  line L116 (55.0016, 10.929) -> (53.6085, 12.8264)
  line L117 (54.0891, 18.7879) -> (54.9649, 20.5944)
  line L118 (56.4165, 19.8907) -> (55.5408, 18.0841)
  line L119 (54.815, 18.436) -> (55.6907, 20.2426)
  line L120 (52.1939, 19.1927) -> (51.5024, 20.1347)
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  parallel L6 L7
  parallel L9 L10
  parallel L12 L13
  parallel L15 L16
  parallel L18 L19
  parallel L21 L22
  parallel L24 L25
  parallel L7 L26
  parallel L27 L28
  parallel L7 L29
  parallel L30 L31
  parallel L33 L34
  parallel L31 L35
  parallel L36 L37
  parallel L35 L38
  parallel L39 L40
  vertical L41
  parallel L42 L43
  parallel L45 L46
  parallel L48 L49
  parallel L51 L52
  parallel L54 L55
  parallel L57 L58
  parallel L60 L61
  perpendicular L57 L62
  parallel L63 L64
  parallel L66 L67
  parallel L69 L70
  parallel L72 L73
  parallel L75 L76
  parallel L78 L79
  parallel L81 L82
  parallel L84 L85
  perpendicular L82 L86
  parallel L87 L88
  parallel L90 L91
  perpendicular L85 L92
  parallel L93 L94
  parallel L96 L97
  parallel L99 L100
  parallel L102 L103
  parallel L105 L106
  parallel L108 L109
  parallel L111 L112
  parallel L114 L115
  parallel L14 L116
  parallel L117 L118
  dimension "d153" diameter = 1
  dimension "d154" diameter = 2
  dimension "d155" diameter = 1
  dimension "d156" diameter = 1
extrude "Extrude19" add sketch "Sketch1" profile of L1 L2 L3 L4 L8 L5 L6 L7 against normal blind 2.8 and against normal blind 1
extrude "Extrude20" cut of existing geometry blind -4
fillet "Fillet19" radius 1
fillet "Fillet20" radius 1
sketch "Sketch17" plane through (0, 0, 1.4) normal (0, 0, -1) x axis (1, 0, 0)
  line L1 (89.7, -20.9875) -> (89.7, -33.6)
  line L2 (87.9, -20.9875) -> (89.7, -20.9875)
  line L3 (87.9, -33.6) -> (87.9, -20.9875)
  line L4 (89.7, -33.6) -> (87.9, -33.6)
  line L5 (87.9, -33.6) -> (89.7, -33.6)
  line L6 (87.9, -20.9875) -> (87.9, -33.6)
  line L7 (89.7, -20.9875) -> (87.9, -20.9875)
  line L8 (89.7, -33.6) -> (89.7, -20.9875)
  line L9 (89.7, -20.9875) -> (87.9, -20.9875)
  line L10 (89.7, -20.9975) -> (89.7, -20.9875)
  line L11 (87.9, -20.9975) -> (89.7, -20.9975)
  line L12 (87.9, -20.9875) -> (87.9, -20.9975)
  point P4 (87.9, -20.9875)
  point P8 (87.9, -20.9875)
  point P2 (89.7, -33.6)
  point P6 (89.7, -33.6)
  point P12 (87.9, -20.9975)
  horizontal L5
  vertical L6
  horizontal L7
  vertical L8
  coincident P4 P8
  coincident P2 P6
  horizontal L9
  vertical L10
  horizontal L11
  vertical L12
  dimension "d173" distance P8 P12 = 0.01
extrude "Extrude21" new body sketch "Sketch17" profile of L1 L2 L3 L4 L5 L6 L7 L8 along normal blind 4.2 and along normal blind 0.2
extrude "Extrude22" add sketch "Sketch17" profile of L1 L2 L3 L6 L7 L8 L9 L10 L11 L12 along normal blind 0.28
extrude "Extrude23" cut of existing geometry blind -4.2
delete_face "DeleteFace1"
delete_face "DeleteFace2"
sketch "Sketch19" plane through (87.9, 0, 0) normal (-1, 0, 0) x axis (0, -1, 0)
  line L1 (-20.9875, 1.4) -> (-33.6, 1.4)
  line L2 (-19.9875, -1) -> (-19.9875, 0.4)
  line L3 (-2.4862, -1) -> (-19.9875, -1)
  line L4 (-2.4862, 23.1) -> (-2.4862, -1)
  line L5 (-53.502, 23.1) -> (-2.4862, 23.1)
  line L6 (-53.502, -1) -> (-53.502, 23.1)
  line L7 (-34.6, -1) -> (-53.502, -1)
  line L8 (-34.6, 0.4) -> (-34.6, -1)
  line L9 (-39.9941, 23.1) -> (-27.9941, 23.1)
  line L10 (-39.9941, 21.6) -> (-39.9941, 23.1)
  line L11 (-27.9941, 21.6) -> (-39.9941, 21.6)
  line L12 (-27.9941, 23.1) -> (-27.9941, 21.6)
  line L13 (-15.9941, 23.1) -> (-27.9941, 23.1)
  line L14 (-15.9941, 21.6) -> (-15.9941, 23.1)
  line L15 (-27.9941, 21.6) -> (-15.9941, 21.6)
  line L16 (-27.9941, 23.1) -> (-27.9941, 21.6)
  line L17 (-15.9941, 23.1) -> (-14.4941, 23.1)
  arc A1 centre (-20.9875, 0.4) radius 1 clockwise from (-20.9875, 1.4) to (-19.9875, 0.4)
  arc A2 centre (-33.6, 0.4) radius 1 clockwise from (-34.6, 0.4) to (-33.6, 1.4)
  arc A3 centre (-15.9941, 23.1) radius 1.5 clockwise from (-14.4941, 23.1) to (-15.9941, 21.6)
  arc A4 centre (-39.9941, 23.1) radius 1.5 clockwise from (-39.9941, 21.6) to (-41.4941, 23.1)
  point P17 (-27.9941, 23.1)
  point P25 (-14.4941, 23.1)
  point P21 (-15.9941, 23.1)
  point P24 (-15.9941, 23.1)
  point P18 (-39.9941, 23.1)
  point P26 (-39.9941, 23.1)
  point P20 (-27.9941, 21.6)
  point P23 (-27.9941, 21.6)
  horizontal L9
  vertical L10
  horizontal L11
  vertical L12
  midpoint L5 P17
  horizontal L13
  vertical L14
  horizontal L15
  vertical L16
  coincident L5 P25
  coincident P21 P24
  coincident P18 P26
  dimension "d182" distance P17 P18 = 12
  dimension "d183" distance P17 P20 = 1.5
  dimension "d184" distance P17 P23 = 1.5
revolve "Revolve2" sketch "Sketch19" AlongAngle 360
fillet "Fillet21" radius 0.5
sketch "Sketch20" plane through (0, 57.002, 0) normal (0, -1, 0) x axis (1, 0, 0)
  line L1 (84.4, 23.1) -> (84.4, -1)
  line L2 (4.4, 23.1) -> (84.4, 23.1)
  line L3 (4.4, -1) -> (4.4, 23.1)
  line L4 (84.4, -1) -> (4.4, -1)
  line L5 (80.55, 3) -> (80.55, 6.3)
  line L6 (71.05, 2.5) -> (80.05, 2.5)
  line L7 (70.55, 6.3) -> (70.55, 3)
  line L8 (80.05, 6.8) -> (71.05, 6.8)
  line L9 (51.5, 3) -> (51.5, 6)
  line L10 (43.9, 2.5) -> (51, 2.5)
  line L11 (43.4, 6) -> (43.4, 3)
  line L12 (51, 6.5) -> (43.9, 6.5)
  line L13 (64.85, 3) -> (64.85, 6)
  line L14 (57.25, 2.5) -> (64.35, 2.5)
  line L15 (56.75, 6) -> (56.75, 3)
  line L16 (64.35, 6.5) -> (57.25, 6.5)
  line L17 (4.4, 21.1) -> (4.4, 23.1)
  line L18 (84.3868, 22.1) -> (4.4, 22.1)
  line L19 (44.3934, 28.369) -> (44.3934, 22.1)
  circle C1 centre (33.2511, 6.0518) radius 3.5
  arc A1 centre (80.05, 3) radius 0.5 clockwise from (80.55, 3) to (80.05, 2.5)
  arc A2 centre (71.05, 3) radius 0.5 clockwise from (71.05, 2.5) to (70.55, 3)
  arc A3 centre (71.05, 6.3) radius 0.5 clockwise from (70.55, 6.3) to (71.05, 6.8)
  arc A4 centre (80.05, 6.3) radius 0.5 clockwise from (80.05, 6.8) to (80.55, 6.3)
  arc A5 centre (51, 3) radius 0.5 clockwise from (51.5, 3) to (51, 2.5)
  arc A6 centre (43.9, 3) radius 0.5 clockwise from (43.9, 2.5) to (43.4, 3)
  arc A7 centre (43.9, 6) radius 0.5 clockwise from (43.4, 6) to (43.9, 6.5)
  arc A8 centre (51, 6) radius 0.5 clockwise from (51, 6.5) to (51.5, 6)
  arc A9 centre (64.35, 3) radius 0.5 clockwise from (64.85, 3) to (64.35, 2.5)
  arc A10 centre (57.25, 3) radius 0.5 clockwise from (57.25, 2.5) to (56.75, 3)
  arc A11 centre (57.25, 6) radius 0.5 clockwise from (56.75, 6) to (57.25, 6.5)
  arc A12 centre (64.35, 6) radius 0.5 clockwise from (64.35, 6.5) to (64.85, 6)
  point P4 (4.4, 23.1)
  point P45 (4.4, 23.1)
  point P47 (4.4, 22.1)
  point P49 (44.3934, 22.1)
  point P46 (4.4, 21.1)
  coincident P4 P45
  perpendicular L2 L17
  horizontal L18
  midpoint L17 P47
  midpoint L18 P49
  perpendicular L18 L19
  dimension "d188" distance P45 P46 = 2
sphere_primitive "SpherePrimitive1" sketch "Sketch20" Diameter 2
move "Move1"
sketch "Sketch24" plane through (0, 0, -1) normal (0, 0, 1) x axis (-1, 0, 0)
  line L1 (-28.4308, -0.6684) -> (-80.403, -0.6684)
  line L2 (-28.4308, -6.4876) -> (-28.4308, -0.6684)
  line L3 (-80.403, -6.4876) -> (-28.4308, -6.4876)
  line L4 (-80.403, -0.6684) -> (-80.403, -6.4876)
  circle C1 centre (-25.4086, -3.5211) radius 1.375
  horizontal L1
  vertical L2
  horizontal L3
  vertical L4
extrude "Extrude24" cut sketch "Sketch24" profile of L1 L2 L3 L4 against normal blind 1
extrude "Extrude25" cut of existing geometry blind -0.003
extrude "Extrude26" cut of existing geometry blind -0.098
fillet "Fillet22" radius 1
fillet "Fillet23" radius 0.5
delete_face "DeleteFace3"
delete_face "DeleteFace4"
path_pattern "PathPattern1" countU 30 PathPatternDelta 276.261
delete_face "DeleteFace5"
delete_face "DeleteFace6"
delete_face "DeleteFace7"
delete_face "DeleteFace8"
sketch "Sketch25" plane through (0, 0, 23.1) normal (0, 0, 1) x axis (-1, 0, 0)
  line L1 (-87.9, -2.4862) -> (-87.9, -14.0576)
  line L2 (-4.4, 1.0138) -> (-84.4, 1.0138)
  line L3 (-0.9, -53.502) -> (-0.9, -2.4862)
  line L4 (-84.4, -57.002) -> (-4.4, -57.002)
  line L5 (-87.9, -41.9306) -> (-87.9, -53.502)
  line L6 (-89.2, -53.302) -> (-89.2, -41.4294)
  line L7 (-4.6, -58.302) -> (-84.2, -58.302)
  line L8 (0.4, -2.6862) -> (0.4, -53.302)
  line L9 (-84.2, 2.3138) -> (-4.6, 2.3138)
  line L10 (-89.2, -14.5589) -> (-89.2, -2.6862)
  line L11 (-87.9, -41.9306) -> (-87.9, -14.0576)
  arc A1 centre (-87.9, -15.9941) radius 1.9365 clockwise from (-89.2, -14.5589) to (-87.9, -14.0576)
  arc A2 centre (-84.4, -2.4862) radius 3.5 clockwise from (-87.9, -2.4862) to (-84.4, 1.0138)
  arc A3 centre (-4.4, -2.4862) radius 3.5 clockwise from (-4.4, 1.0138) to (-0.9, -2.4862)
  arc A4 centre (-4.4, -53.502) radius 3.5 clockwise from (-0.9, -53.502) to (-4.4, -57.002)
  arc A5 centre (-84.4, -53.502) radius 3.5 clockwise from (-84.4, -57.002) to (-87.9, -53.502)
  arc A6 centre (-87.9, -39.9941) radius 1.9365 clockwise from (-87.9, -41.9306) to (-89.2, -41.4294)
  arc A7 centre (-84.2, -53.302) radius 5 clockwise from (-84.2, -58.302) to (-89.2, -53.302)
  arc A8 centre (-4.6, -53.302) radius 5 clockwise from (0.4, -53.302) to (-4.6, -58.302)
  arc A9 centre (-4.6, -2.6862) radius 5 clockwise from (-4.6, 2.3138) to (0.4, -2.6862)
  arc A10 centre (-84.2, -2.6862) radius 5 clockwise from (-89.2, -2.6862) to (-84.2, 2.3138)
  point P2 (-87.9, -14.0576)
  point P32 (-87.9, -14.0576)
  point P17 (-87.9, -41.9306)
  point P33 (-87.9, -41.9306)
  coincident P2 P32
  coincident P17 P33
extrude "Extrude27" new body sketch "Sketch25" profile of L1 A2 L2 A3 L3 A4 L4 A5 L5 L11 along normal blind 1
combine "Combine1"
sketch "Sketch26" plane through (0, 0, -1) normal (0, 0, 1) x axis (-1, 0, 0)
  circle C1 centre (-25.4086, -3.5211) radius 1.375
  circle C2 centre (-25.4086, -3.5211) radius 1.2
  circle C3 centre (-83.4, -3.5) radius 1.2
  circle C4 centre (-83.4, -3.5) radius 1.375
  circle C5 centre (-83.4, -52.5) radius 1.2
  circle C6 centre (-83.4, -52.5) radius 1.375
  circle C7 centre (-25.4038, -52.5109) radius 1.2
  circle C8 centre (-25.4038, -52.5109) radius 1.375
  concentric C1 C2
  concentric C3 C4
  concentric C5 C6
  concentric C7 C8
  dimension "d204" diameter C2 = 2.4
  dimension "d205" diameter C3 = 2.4
  dimension "d206" diameter C5 = 2.4
  dimension "d207" diameter C7 = 2.4
extrude "Extrude28" new body sketch "Sketch26" profile of C2 C3 C5 C7 along normal blind 3.75
fillet "Fillet24" radius 1
sketch "Sketch27" plane through (0, 0, 2.75) normal (0, 0, 1) x axis (-1, 0, 0)
  circle C1 centre (-83.4, -52.5) radius 1.2
  circle C2 centre (-25.4, -3.5) radius 3
  circle C3 centre (-83.4, -3.5) radius 3
  circle C4 centre (-83.4, -3.5) radius 1.2
  circle C5 centre (-83.4, -52.5) radius 3
  circle C6 centre (-25.4, -52.5) radius 3
  concentric C3 C4
  concentric C1 C5
  dimension "d212" diameter C2 = 6
  dimension "d213" diameter C3 = 6
  dimension "d214" diameter C5 = 6
  dimension "d215" diameter C6 = 6
extrude "Extrude29" add sketch "Sketch27" along normal blind 16.5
